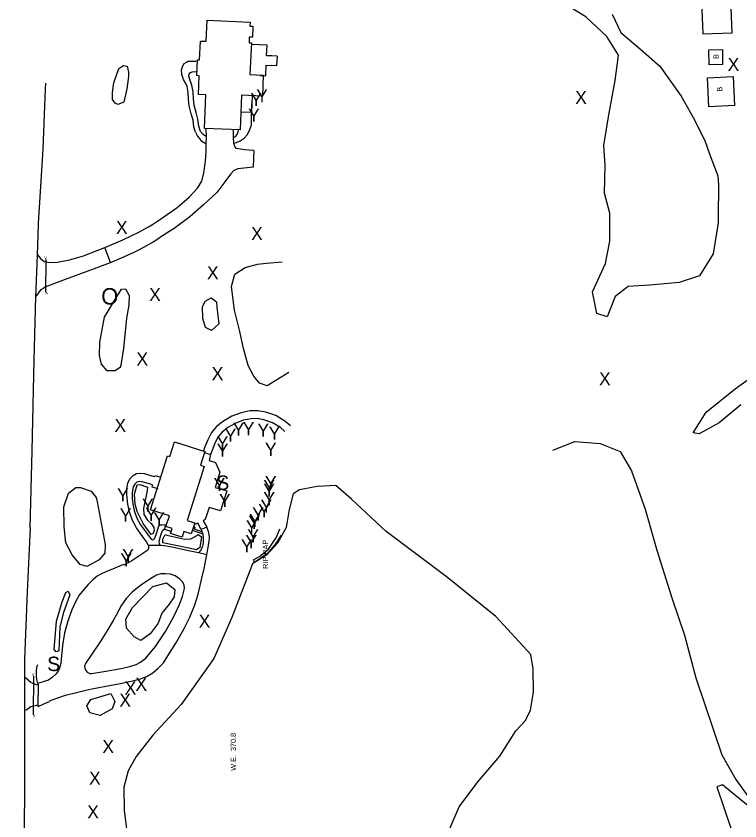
# Model space of a CAD drawing. Extents: x 2030130 to 2036320, y 723205 to 762423.
# Drawn here: x 2031299 to 2031851, y 728217 to 728830 of the extents above; entities that cross this region are included whole.
import ezdxf

# ---------------------------------------------------------------- set-up
doc = ezdxf.new("R2010")
doc.units = 0
for name, color, linetype in [('Draft_Station Cardinal Points', 7, 'Continuous'), ('Draft_Station Labels Major', 7, 'Continuous'), ('Draft_Station Tics Major', 7, 'Continuous'), ('Draft_Station Tics Minor', 7, 'Continuous'), ('Exist Terrain Model Ground Surface', 7, 'Continuous'), ('Old_Level_28', 7, 'Continuous'), ('Prop Alignment Horizontal', 7, 'Continuous'), ('Prop Alignment Vertical', 7, 'Continuous')]:
    doc.layers.add(name, color=color, linetype=linetype)

msp = doc.modelspace()

# ---------------------------------------------------------------- linework, layer by layer
at = {"layer": 'Draft_Station Labels Major'}
for p, q in [((2031443.62, 728738.23), (2031443.61, 728744.68)), ((2031443.48, 728732.95), (2031443.62, 728738.23)), ((2031464.57, 728733.51), (2031464.25, 728737.93)), ((2031370.49, 728642.62), (2031366.18, 728653.99)), ((2031356.8, 728344.76), (2031351.43, 728336.92)), ((2031314.2, 728320.71), (2031315.27, 728321.21)), ((2031315.27, 728321.21), (2031315.13, 728304.72)), ((2031314.08, 728305.26), (2031315.13, 728304.72))]:
    msp.add_line(p, q, dxfattribs=at)
for points in [[(2031320.95, 728774.76), (2031321.13, 728779.28)], [(2031319.09, 728729.08), (2031320.95, 728774.76)], [(2031464.25, 728737.93), (2031464.23, 728741.31), (2031464.23, 728743.78)], [(2031315.43, 728663.11), (2031315.72, 728672.45), (2031317.11, 728696.31), (2031319.09, 728729.08)], [(2031403.2, 728672.05), (2031408.69, 728675.57), (2031421.27, 728684.5), (2031430.48, 728692.36), (2031436.89, 728699.23), (2031440.2, 728704.61), (2031441.75, 728710.9), (2031442.85, 728719.82), (2031443.51, 728727.47), (2031443.48, 728732.95)], [(2031479.78, 728728.01), (2031472.79, 728728.35), (2031466.67, 728729.34), (2031465.33, 728730.95), (2031464.57, 728733.51)], [(2031479.78, 728728.01), (2031479.23, 728715.17), (2031467.72, 728713.99), (2031464.53, 728712.73), (2031461.97, 728709.96), (2031457.84, 728704.12), (2031451.62, 728696.03), (2031441.41, 728686.51), (2031430.99, 728677.45), (2031418.97, 728668.59), (2031408.2, 728661.67)], [(2031366.18, 728653.99), (2031380.03, 728659.78), (2031392.68, 728665.97), (2031399.61, 728669.74), (2031403.2, 728672.05)], [(2031314.86, 728648.53), (2031315.43, 728663.11)], [(2031391.05, 728651.73), (2031396.44, 728654.46), (2031403.14, 728658.26), (2031408.2, 728661.67)], [(2031314.86, 728648.53), (2031317.08, 728645.51), (2031319.98, 728643.24), (2031323.89, 728642.61), (2031330.16, 728642.91), (2031339.18, 728644.67), (2031350.06, 728647.74), (2031366.18, 728653.99)], [(2031370.49, 728642.62), (2031378.96, 728646.15), (2031389.19, 728650.73), (2031391.05, 728651.73)], [(2031313.66, 728616.51), (2031313.83, 728622.49), (2031314.86, 728648.53)], [(2031313.66, 728616.51), (2031317.75, 728622.01), (2031320.67, 728624.11), (2031336.28, 728629.87), (2031358.28, 728637.91), (2031370.49, 728642.62)], [(2031309.31, 728440.35), (2031310.72, 728499.03), (2031312.26, 728568.48), (2031313.66, 728616.51)], [(2031309.31, 728440.35), (2031307, 728391.57), (2031305.02, 728340.19), (2031304.93, 728288.69), (2031304.95, 728234.79), (2031304.12, 728185.29), (2031302.56, 728133.97), (2031301.6, 728083.06), (2031303.32, 728030.13), (2031300.9, 727978.33), (2031299.77, 727928.62), (2031298.86, 727876.87), (2031298.53, 727850.76)], [(2031398.99, 728423.42), (2031392.96, 728419.27), (2031386.85, 728415.31), (2031380.68, 728412)], [(2031408.7, 728426.91), (2031399.45, 728426.96), (2031399.5, 728425.8), (2031399.42, 728424.65), (2031398.99, 728423.42)], [(2031443.88, 728419.76), (2031437.57, 728421.28), (2031430.06, 728422.89), (2031419.96, 728425.13), (2031413.36, 728426.33), (2031411.3, 728426.54), (2031408.7, 728426.91)], [(2031323.93, 728308.5), (2031329.5, 728310.54), (2031336.2, 728312.72), (2031344.52, 728314.95), (2031351.81, 728316.74), (2031356.26, 728317.53), (2031367.07, 728319.66), (2031379.4, 728321.95), (2031387.42, 728323.62), (2031393.31, 728325.31), (2031398.43, 728327.42), (2031402.72, 728329.93), (2031406.91, 728333.3), (2031410.84, 728337.49), (2031415.5, 728344.79), (2031420.84, 728353.22), (2031426.81, 728363.59), (2031430.99, 728372.29), (2031434.83, 728381.63), (2031437.42, 728389.8), (2031440.26, 728402.08), (2031442.02, 728409.42), (2031443.88, 728419.76)], [(2031380.48, 728412.46), (2031373.84, 728409.57), (2031366.9, 728406.92), (2031363.04, 728405.08), (2031360.47, 728403.55), (2031357.03, 728400.77), (2031353.43, 728397.2), (2031350.24, 728393.46), (2031346.72, 728388.95), (2031344.29, 728384.86), (2031341.13, 728377.92), (2031337.98, 728369.26), (2031335.5, 728360.28), (2031333.92, 728350.62), (2031333.24, 728342.91), (2031332.57, 728336.92), (2031331.37, 728332.75), (2031329.22, 728329.18), (2031326.02, 728326.26), (2031323.25, 728324.34), (2031320.81, 728323.56), (2031315.12, 728321.68)], [(2031397.4, 728341), (2031404.93, 728349.84), (2031412.57, 728361.42), (2031418.69, 728372.22), (2031423.2, 728381.91), (2031425.34, 728388.05), (2031426.85, 728394.22), (2031426.65, 728396.89), (2031425.45, 728399.18), (2031423.37, 728401.33), (2031419.85, 728403.72), (2031416.23, 728405.03), (2031412.59, 728405.41), (2031408.85, 728405.21), (2031405.73, 728404.33), (2031401.83, 728402.09), (2031393.62, 728396.72), (2031386.96, 728391.36), (2031382.51, 728386.52), (2031379.03, 728381.33), (2031374.89, 728373.79), (2031372.63, 728369.73), (2031367.74, 728361.68), (2031362.6, 728353.51), (2031356.8, 728344.76)], [(2031351.43, 728336.92), (2031350.78, 728334.8), (2031351.11, 728332.46), (2031352.67, 728330.41), (2031354.66, 728329.38), (2031356.23, 728329.39), (2031366.98, 728331.06), (2031378.53, 728333.24), (2031385.17, 728334.62), (2031390.02, 728336.16), (2031393.48, 728337.85), (2031397.4, 728341)], [(2031314.2, 728320.71), (2031309.8, 728322.54), (2031305.76, 728326.12)], [(2031315.33, 728304.27), (2031319.76, 728306.24), (2031324.12, 728308.04)], [(2031305.89, 728301.35), (2031309.76, 728304.15), (2031314.08, 728305.26)]]:
    msp.add_lwpolyline(points, dxfattribs=at)
at = {"layer": 'Draft_Station Tics Major'}
for p, q in [((2031384.23, 728784.2), (2031383.06, 728774.82)), ((2031451.35, 728612.61), (2031451.7, 728608.53)), ((2031384.59, 728610), (2031382.63, 728600.02)), ((2031390.82, 728452.69), (2031389.22, 728458.38)), ((2031438.72, 728425.28), (2031436, 728423.7)), ((2031382.16, 728370.72), (2031387.25, 728379.51)), ((2031352.47, 728304.66), (2031355.46, 728309.62))]:
    msp.add_line(p, q, dxfattribs=at)
for points in [[(2031747.3, 728695.53), (2031747.64, 728716.41), (2031746.71, 728731.61), (2031750.21, 728753.58), (2031755.51, 728781.26), (2031757.85, 728800.58), (2031749.13, 728814.77), (2031733, 728829.83), (2031714.26, 728841.29)], [(2031753.08, 728831.73), (2031759.81, 728817.78), (2031775, 728804.96), (2031789.39, 728792.14), (2031805.59, 728769.28), (2031814.99, 728753.11), (2031823.74, 728735.61), (2031827.67, 728724.54), (2031833.76, 728708.6), (2031834.21, 728701.67)], [(2031383.06, 728774.82), (2031380.79, 728764.82), (2031376.07, 728763.06), (2031374.04, 728764.04), (2031372.11, 728766.89), (2031372.06, 728772.06), (2031373.01, 728779.61), (2031376.8, 728790.42), (2031380.35, 728792.68), (2031383.33, 728792.09), (2031384.19, 728787.68), (2031384.23, 728784.2)], [(2031834.21, 728701.67), (2031834.01, 728677.11)], [(2031751.24, 728673.66), (2031751.21, 728680.24), (2031747.3, 728695.53)], [(2031834.01, 728677.11), (2031833.97, 728672.9), (2031830.14, 728649.26), (2031819.81, 728632.32), (2031804.14, 728627.22), (2031781.85, 728625.26), (2031765.36, 728624.38), (2031755.38, 728616.54), (2031749.39, 728601.2), (2031741.46, 728603.8), (2031738.21, 728620.14), (2031748.12, 728641.83), (2031751.32, 728658.74), (2031751.24, 728673.66)], [(2031506.65, 728558.75), (2031489.91, 728548.47), (2031484.2, 728550.68), (2031479.81, 728555.94), (2031475.53, 728564.19), (2031472, 728576.93), (2031469.19, 728589.92), (2031465.12, 728606.22), (2031462.86, 728624.23), (2031465.35, 728633.65), (2031473.2, 728638.88), (2031482.66, 728641.38), (2031489.4, 728642.08), (2031501.41, 728642.96)], [(2031382.63, 728600.02), (2031380.45, 728577.03), (2031378.04, 728562.69), (2031374.17, 728559.9), (2031368.11, 728559.89), (2031363.65, 728565.02), (2031362.11, 728571.68), (2031362.28, 728581.88), (2031365.98, 728600.89), (2031374.47, 728614.84), (2031378.97, 728622.2), (2031381.92, 728622.62), (2031384.7, 728617.53), (2031384.59, 728610)], [(2031451.7, 728608.53), (2031453.24, 728595.76), (2031447.46, 728590.81), (2031443.04, 728593.08), (2031441.02, 728599.8), (2031440.79, 728608.81), (2031442.6, 728612.97), (2031447.3, 728615.67), (2031451.35, 728612.61)], [(2031851.25, 728533.97), (2031834.67, 728520.27), (2031819.52, 728512), (2031814.76, 728512.63), (2031824.85, 728528.55), (2031846.82, 728546.24), (2031881.45, 728571.14)], [(2031707.91, 728499.64), (2031724.52, 728506.07), (2031743.96, 728504.59), (2031759.19, 728498.46), (2031767.73, 728483.83), (2031778.19, 728454.68), (2031787.22, 728423.41), (2031798.65, 728386.99), (2031808.18, 728358.49), (2031816.92, 728325.97), (2031836.71, 728267.45), (2031847.37, 728248.6), (2031858.63, 728233.18)], [(2031389.22, 728458.38), (2031388.77, 728466.11), (2031390.95, 728473.24), (2031392.96, 728473.36), (2031398.73, 728471.46), (2031398.51, 728468.8), (2031395.64, 728455.14), (2031396.05, 728450.6), (2031398.7, 728446.16), (2031401.47, 728443.54), (2031403.67, 728440.65), (2031403.74, 728438.2), (2031403.01, 728435.94), (2031401.55, 728435.32), (2031395.45, 728443.73), (2031390.82, 728452.69)], [(2031360.41, 728460.11), (2031366.55, 728427.68), (2031366.33, 728421.08), (2031361.93, 728415.88), (2031352.46, 728410.82), (2031347.4, 728412.42), (2031341.21, 728419.86), (2031336.36, 728428.9), (2031335.12, 728441.05), (2031335.04, 728456.38), (2031338.4, 728466.81), (2031344, 728471.12), (2031347.62, 728471.18), (2031355.7, 728468.32)], [(2031355.7, 728468.32), (2031359.68, 728463.39), (2031360.41, 728460.11)], [(2031436, 728423.7), (2031430.2, 728424.92), (2031410.54, 728428.83), (2031410.52, 728431.63), (2031412.33, 728435.3), (2031413.38, 728434.87), (2031427.21, 728431.68), (2031431.86, 728431.93), (2031435.14, 728433.75), (2031437.45, 728435.39), (2031439.92, 728433.43), (2031438.72, 728425.28)], [(2031387.25, 728379.51), (2031402.93, 728395.72), (2031413.16, 728398.52), (2031419.67, 728393.46), (2031419.08, 728387.79), (2031415.3, 728382.17), (2031409.76, 728375.26), (2031406.97, 728367.78), (2031400.82, 728359.58), (2031393.59, 728354.44), (2031388.56, 728357.36), (2031382.61, 728363.97), (2031382.16, 728370.72)], [(2031336.5, 728391.13), (2031338.21, 728392.02), (2031339.43, 728389.39)], [(2031339.43, 728389.39), (2031334.75, 728375.71), (2031331.86, 728364.78), (2031331.05, 728346.7), (2031329.01, 728345.89), (2031327.66, 728347.61), (2031329.26, 728369.12), (2031333.7, 728383.92), (2031336.5, 728391.13)], [(2031355.46, 728309.62), (2031370.88, 728314.05), (2031373.8, 728308.05), (2031371.75, 728302.53), (2031362.73, 728297.24), (2031354.7, 728299.39), (2031352.47, 728304.66)], [(2031856.85, 728228.57), (2031846.23, 728237.11), (2031837.34, 728244.46), (2031832.99, 728242.85), (2031843.6, 728211.45), (2031864.79, 728178.66)]]:
    msp.add_lwpolyline(points, dxfattribs=at)
at = {"layer": 'Draft_Station Tics Minor'}
for points in [[(2031321.29, 728619.99), (2031321.58, 728644.95)], [(2031311.81, 728297.88), (2031312.13, 728327.23)]]:
    msp.add_lwpolyline(points, dxfattribs=at)
at = {"layer": 'Exist Terrain Model Ground Surface'}
for p, q in [((2031411.69, 728439.3), (2031412.67, 728442.66)), ((2031412.67, 728442.66), (2031413.22, 728442.47)), ((2031443.88, 728440.77), (2031439.62, 728439.04)), ((2031411.69, 728439.3), (2031416.99, 728437.63))]:
    msp.add_line(p, q, dxfattribs=at)
for points in [[(2031821.03, 728848.33), (2031822.24, 728816.83), (2031844.56, 728817.69), (2031843.35, 728849.19)], [(2031444.18, 728827.27), (2031477, 728825.85), (2031476.86, 728822.75), (2031479.18, 728822.65), (2031478.82, 728814.3), (2031476.4, 728814.41), (2031476.21, 728810.1), (2031477.94, 728810.02), (2031476.89, 728785.84), (2031487.06, 728785.4), (2031486.36, 728769.33), (2031470.55, 728770.01), (2031469.4, 728743.56), (2031442.09, 728744.74), (2031443.2, 728770.31), (2031437.54, 728770.55), (2031438.17, 728784.9), (2031436.25, 728784.98), (2031436.77, 728797.06), (2031438.45, 728796.99), (2031439.07, 728811.37), (2031443.49, 728811.18)], [(2031826.9, 728804.74), (2031837.18, 728804.84), (2031837.29, 728793.37), (2031827, 728793.27)], [(2031825.84, 728783.37), (2031845.41, 728784.34), (2031846.5, 728762.28), (2031826.93, 728761.31)], [(2031442.05, 728487.19), (2031428.96, 728445.95), (2031434.75, 728444.11), (2031432.08, 728435.7), (2031426.58, 728437.45), (2031425.26, 728433.27), (2031416.41, 728436.08), (2031417.57, 728439.74), (2031412.83, 728441.24), (2031415.47, 728449.56), (2031401.02, 728454.15), (2031414.07, 728495.26), (2031415.82, 728494.7), (2031419.4, 728505.96), (2031442.54, 728498.61), (2031439.21, 728488.09)]]:
    msp.add_lwpolyline(points, close=True, dxfattribs=at)
for points in [[(2031497.57, 728799.86), (2031493.67, 728799.96), (2031489.59, 728800.17), (2031489.98, 728808.26), (2031477.89, 728808.78)], [(2031497.57, 728799.86), (2031497.23, 728792.4), (2031493.35, 728792.68)], [(2031428.07, 728779), (2031426.27, 728782.15), (2031424.93, 728785.76), (2031424.74, 728789.06), (2031425.33, 728791.94), (2031426.64, 728794.25), (2031428.45, 728795.28), (2031429.86, 728795.95), (2031431.62, 728796.05), (2031435.87, 728796)], [(2031484.56, 728785.05), (2031488.92, 728784.95), (2031489.31, 728792.88), (2031493.35, 728792.68)], [(2031443.62, 728738.23), (2031441.13, 728740.11), (2031439.1, 728742.49), (2031437.85, 728746.52), (2031437.19, 728751.86), (2031435.75, 728756.98), (2031434.3, 728762.57), (2031433.74, 728767.18), (2031433.49, 728772.55), (2031432.57, 728777.76), (2031430.92, 728782.14), (2031430.36, 728784.84), (2031430.58, 728786.12), (2031431.64, 728787.4), (2031432.2, 728787.74), (2031432.8, 728787.88), (2031435.88, 728788.19)], [(2031435.32, 728741.98), (2031434.16, 728745.72), (2031433.49, 728751.11), (2031432.11, 728755.99), (2031430.59, 728761.86), (2031429.98, 728766.86), (2031429.74, 728772.13), (2031428.92, 728776.76), (2031428.07, 728779)], [(2031470, 728757.5), (2031478.37, 728757.14), (2031478.85, 728769.65)], [(2031464.57, 728733.51), (2031466.64, 728734.13), (2031469.46, 728735.29), (2031472.44, 728737.24), (2031474.65, 728739.86), (2031476.59, 728743.09), (2031478, 728747.38), (2031478.1, 728751.13), (2031478.4, 728763.41)], [(2031435.32, 728741.98), (2031436.78, 728738.8), (2031439.15, 728736.03), (2031441.13, 728734.36), (2031443.48, 728732.95)], [(2031464.25, 728737.93), (2031465.78, 728738.62), (2031467.24, 728740.09), (2031467.97, 728742.1), (2031468.04, 728743.62)], [(2031507.87, 728518.01), (2031503.6, 728521.6), (2031496.49, 728525.85), (2031489.04, 728528.44), (2031482.8, 728529.64), (2031477.11, 728529.44), (2031470.09, 728528.08), (2031463.04, 728525.37), (2031456.61, 728521.73), (2031451.47, 728517.64), (2031447.66, 728512.94), (2031444.79, 728507.53), (2031442.58, 728502.16), (2031441.5, 728498.94)], [(2031503.55, 728513.82), (2031500.11, 728516.71), (2031493.95, 728520.4), (2031487.48, 728522.64), (2031482.33, 728523.63), (2031477.79, 728523.47), (2031471.74, 728522.3), (2031465.6, 728519.94), (2031459.98, 728516.75), (2031455.71, 728513.36), (2031452.68, 728509.62), (2031450.22, 728504.98), (2031448.19, 728500.07), (2031446.91, 728496.23)], [(2031442.28, 728497.78), (2031446.91, 728496.23), (2031445.73, 728491.67), (2031450.58, 728490.24), (2031453.91, 728482.72), (2031450.4, 728471.12), (2031459.31, 728468.45), (2031454.48, 728453.35), (2031445.75, 728455.87), (2031442.84, 728446.72), (2031441.13, 728445.79), (2031443.88, 728440.77)], [(2031399.45, 728426.96), (2031397.96, 728429.65), (2031394.66, 728434.17), (2031390.4, 728440.31), (2031387.31, 728445.93), (2031385.03, 728452.57), (2031383.63, 728458.32), (2031383.01, 728465.68), (2031383.03, 728470.03), (2031383.78, 728474.42), (2031385.36, 728477.8), (2031387.87, 728480.34), (2031390.24, 728481.68), (2031393.62, 728482.07), (2031396.29, 728481.68), (2031403.87, 728479.41)], [(2031403.87, 728479.41), (2031404.2, 728479.23), (2031404.48, 728480.22), (2031408.87, 728479.03)], [(2031401.37, 728473.65), (2031394.32, 728475.52), (2031392.29, 728475.6), (2031390.65, 728475.19), (2031389.08, 728473.73), (2031387.9, 728471.62), (2031386.96, 728467.35), (2031387.07, 728462.52), (2031387.58, 728458.52), (2031388.69, 728453.56), (2031390.73, 728447.84), (2031393.53, 728442.68), (2031397.86, 728436.59), (2031401.62, 728431.77), (2031402.71, 728431.31), (2031403.67, 728431.68), (2031404.33, 728432.46), (2031405.79, 728436.7), (2031407.18, 728441.14), (2031408.26, 728442.53), (2031409.83, 728442.7), (2031411.09, 728442.85), (2031412.67, 728442.66)], [(2031401.37, 728473.65), (2031402.44, 728473.13), (2031401.95, 728471.71), (2031406.56, 728470.33)], [(2031440.25, 728437.39), (2031434.68, 728439.41), (2031435.15, 728440.79), (2031433.84, 728441.23)], [(2031439.62, 728439.04), (2031437.17, 728443.8), (2031435.13, 728442.84), (2031434.41, 728443.03)], [(2031443.88, 728419.76), (2031445.79, 728429.82), (2031446.05, 728432.92), (2031445.71, 728435.03), (2031445.16, 728437.44), (2031443.88, 728440.77)], [(2031408.7, 728426.91), (2031407.9, 728428.18), (2031407.68, 728430.11), (2031408.89, 728434.86), (2031410.15, 728438.2), (2031411.14, 728439.01), (2031411.69, 728439.3)], [(2031440.84, 728435.41), (2031436.08, 728437.31), (2031432.94, 728438.38)], [(2031439.62, 728439.04), (2031440.84, 728435.41), (2031441.27, 728432.34), (2031441.23, 728429.53), (2031440.57, 728426.46), (2031439.46, 728423.42), (2031437.66, 728421.42)], [(2031500.56, 728434.74), (2031496.37, 728428.15), (2031490.46, 728421.03), (2031485.12, 728417.15), (2031480.3, 728414.03), (2031479.86, 728416.31), (2031484.21, 728418.6), (2031491.07, 728423.98), (2031497.16, 728433.22), (2031499.55, 728439.62)], [(2031315.12, 728321.68), (2031314.42, 728324.67), (2031314.08, 728327.67), (2031314.06, 728331.04), (2031314.36, 728334.26), (2031315.05, 728336.28)]]:
    msp.add_lwpolyline(points, dxfattribs=at)
at = {"layer": 'Prop Alignment Horizontal'}
msp.add_lwpolyline([(2031629.23, 728211.1), (2031636.46, 728227.61), (2031650.58, 728246.89), (2031667.54, 728266.42), (2031679.76, 728285.69), (2031687.07, 728293.55), (2031690.82, 728301.39), (2031693.12, 728315.15), (2031692.79, 728332.93), (2031691.07, 728343.83), (2031664.36, 728372.84), (2031626.51, 728403.22), (2031580.81, 728437.59), (2031569.61, 728447.96), (2031554.36, 728462.1), (2031542.45, 728472.7), (2031528.23, 728471.92), (2031514.73, 728469.24), (2031509.77, 728466.36), (2031506.75, 728454.26), (2031504.46, 728440.73), (2031497.88, 728428.61), (2031489.87, 728419.79), (2031478.77, 728412.86), (2031463.1, 728372), (2031449.28, 728340.87), (2031424.34, 728305.65), (2031402.89, 728282.31), (2031390.18, 728266.12), (2031384.07, 728255.18), (2031380.59, 728242.6), (2031380.92, 728224.58), (2031383.18, 728207.41)], dxfattribs=at)

# ---------------------------------------------------------------- texts
at = {"layer": 'Draft_Station Cardinal Points'}
msp.add_text('O', height=12.5, dxfattribs=at).set_placement((2031363.45, 728610.55))
at = {"layer": 'Draft_Station Tics Major'}
for s, p in [('X', (2031841.16, 728788.51)), ('Y', (2031481.6, 728764.61)), ('X', (2031724.87, 728763.34)), ('Y', (2031477.18, 728761.78)), ('Y', (2031475.41, 728749.9)), ('X', (2031374.66, 728664.28)), ('X', (2031477.73, 728659.66)), ('X', (2031444.06, 728629.72)), ('X', (2031399.99, 728613.13)), ('X', (2031390.32, 728564.04)), ('X', (2031447.69, 728552.83)), ('X', (2031743.06, 728548.96)), ('X', (2031373.54, 728513.42)), ('Y', (2031463.69, 728510.55)), ('Y', (2031471.35, 728510.89)), ('Y', (2031457.6, 728505.94)), ('Y', (2031482.58, 728509.79)), ('Y', (2031491.07, 728507.56)), ('Y', (2031451.5, 728500.14)), ('Y', (2031451.53, 728494.51)), ('Y', (2031488.27, 728495.21)), ('Y', (2031449.13, 728468.32)), ('Y', (2031488.26, 728469.8)), ('Y', (2031487.05, 728466.82)), ('Y', (2031487.06, 728464.02)), ('Y', (2031375.52, 728460.48)), ('Y', (2031453.23, 728456.26)), ('Y', (2031487.1, 728457.55)), ('Y', (2031394.53, 728452.64)), ('Y', (2031484.9, 728451.8)), ('Y', (2031377.61, 728445.09)), ('Y', (2031397.08, 728445.64)), ('Y', (2031478.59, 728445.85)), ('Y', (2031483.19, 728448.42)), ('Y', (2031403.09, 728442.2)), ('Y', (2031475.72, 728439.54)), ('Y', (2031476.18, 728440.97)), ('Y', (2031473.74, 728436.17)), ('Y', (2031473.42, 728424.78)), ('Y', (2031474.8, 728429.22)), ('Y', (2031470, 728421.57)), ('Y', (2031379.44, 728414.25)), ('Y', (2031378.1, 728410.92)), ('X', (2031437.77, 728364.22)), ('X', (2031389.55, 728316.07)), ('X', (2031381.29, 728313.28)), ('X', (2031377.26, 728304.02)), ('X', (2031364.31, 728268.67)), ('X', (2031354.15, 728244.6)), ('X', (2031352.77, 728218.92))]:
    msp.add_text(s, height=10, dxfattribs=at).set_placement(p)
at = {"layer": 'Draft_Station Tics Minor'}
for rotation, p in [(359.5787, (2031320.08, 728644.96)), (179.097, (2031322.79, 728619.96)), (359.62043, (2031310.63, 728327.24)), (179.13873, (2031313.32, 728297.86))]:
    msp.add_text('v', height=2.65, rotation=rotation, dxfattribs=at).set_placement(p)
at = {"layer": 'Exist Terrain Model Ground Surface'}
for p in [(2031451.28, 728469.25), (2031322.29, 728331.18)]:
    msp.add_text('S', height=11, dxfattribs=at).set_placement(p)
at = {"layer": 'Old_Level_28'}
for s, rotation, p in [('B', 88.75344, (2031834.33, 728797.66)), ('B', 93.09612, (2031837.15, 728772.93)), ('RIP RAP', 90.31518, (2031490.78, 728409.14))]:
    msp.add_text(s, height=4, rotation=rotation, dxfattribs=at).set_placement(p)
at = {"layer": 'Prop Alignment Vertical'}
msp.add_text('W.E.  370.8', height=4, rotation=90.30569, dxfattribs=at).set_placement((2031466.32, 728255.21))

doc.saveas('drawing.dxf')
